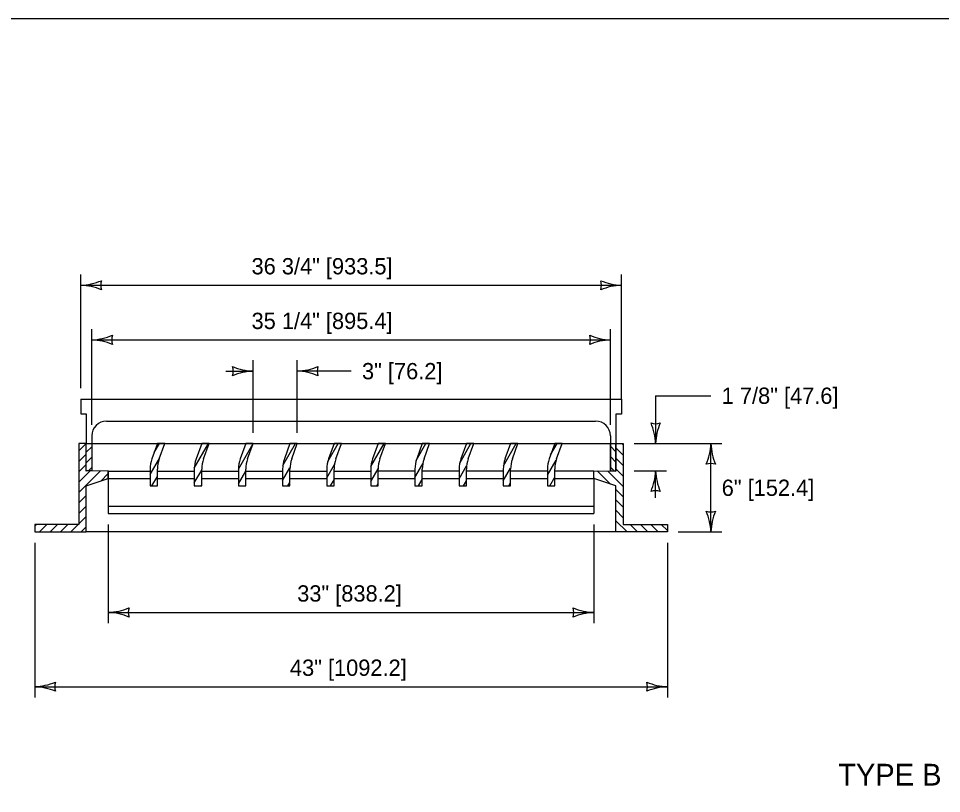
# Model space of a CAD drawing. Extents: x 49991.4 to 50057, y 49987.6 to 50011.4.
# Drawn here: x 50008.526 to 50011.925, y 49996.146 to 49998.999 of the extents above; entities that cross this region are included whole.
import ezdxf

# ---------------------------------------------------------------- set-up
doc = ezdxf.new("R2010")
doc.units = 0
for name, color, linetype in [('Level 1', 7, 'Continuous'), ('Level 2', 7, 'Continuous'), ('Level 3', 7, 'Continuous')]:
    doc.layers.add(name, color=color, linetype=linetype)

msp = doc.modelspace()

# ---------------------------------------------------------------- linework, layer by layer
at = {"layer": 'Level 1'}
for p, q in [((50008.7559, 49997.598), (50008.7559, 49997.5439)), ((50008.7559, 49997.598), (50010.7465, 49997.598)), ((50010.7465, 49997.598), (50010.7465, 49997.5421)), ((50008.7559, 49997.5439), (50008.7762, 49997.5438)), ((50008.7762, 49997.5438), (50008.7762, 49997.4338)), ((50010.7262, 49997.5421), (50010.7262, 49997.4338)), ((50010.7465, 49997.5421), (50010.7262, 49997.5421)), ((50008.8507, 49997.5167), (50010.6518, 49997.5167)), ((50008.7965, 49997.4625), (50008.7965, 49997.4338)), ((50010.7059, 49997.4625), (50010.7059, 49997.3337)), ((50008.7491, 49997.4068), (50008.7761, 49997.4338)), ((50008.7762, 49997.4018), (50008.7965, 49997.4221)), ((50008.7965, 49997.4338), (50010.7059, 49997.4338)), ((50008.7965, 49997.4338), (50008.7965, 49997.3337)), ((50009.0266, 49997.4008), (50009.0456, 49997.4338)), ((50009.174, 49997.3439), (50009.226, 49997.4338)), ((50009.3365, 49997.34), (50009.3906, 49997.4338)), ((50009.4998, 49997.3534), (50009.5462, 49997.4338)), ((50009.6651, 49997.3679), (50009.7031, 49997.4338)), ((50009.8243, 49997.3491), (50009.8732, 49997.4338)), ((50009.9911, 49997.3715), (50010.027, 49997.4338)), ((50010.1513, 49997.3625), (50010.1924, 49997.4338)), ((50010.3121, 49997.3518), (50010.3594, 49997.4338)), ((50010.4858, 49997.392), (50010.51, 49997.4338)), ((50010.7059, 49997.4243), (50010.7262, 49997.404)), ((50010.7262, 49997.4181), (50010.7533, 49997.3911)), ((50010.7488, 49997.4338), (50010.7533, 49997.4294)), ((50008.7491, 49997.3685), (50008.7762, 49997.3956)), ((50008.7762, 49997.3635), (50008.7965, 49997.3838)), ((50009.0115, 49997.3205), (50009.0465, 49997.3812)), ((50010.474, 49997.3173), (50010.5061, 49997.3729)), ((50010.7059, 49997.386), (50010.7262, 49997.3657)), ((50010.7262, 49997.3798), (50010.7533, 49997.3528)), ((50008.7491, 49997.3302), (50008.7762, 49997.3573)), ((50008.7848, 49997.3337), (50008.7965, 49997.3455)), ((50009.174, 49997.2896), (50009.2011, 49997.3365)), ((50009.499, 49997.2978), (50009.5262, 49997.3449)), ((50009.6615, 49997.3075), (50009.6898, 49997.3566)), ((50009.824, 49997.2943), (50009.8511, 49997.3413)), ((50009.9865, 49997.3094), (50010.0152, 49997.3592)), ((50010.149, 49997.3044), (50010.1767, 49997.3525)), ((50010.3115, 49997.2966), (50010.3386, 49997.3436)), ((50010.7059, 49997.3477), (50010.7213, 49997.3323)), ((50010.7262, 49997.3415), (50010.7533, 49997.3144)), ((50008.7491, 49997.2536), (50008.8288, 49997.3333)), ((50008.7491, 49997.2919), (50008.7897, 49997.3325)), ((50008.8298, 49997.296), (50008.8574, 49997.3236)), ((50008.8524, 49997.3035), (50008.8524, 49997.3052)), ((50008.8574, 49997.3323), (50009.0118, 49997.3324)), ((50008.8574, 49997.3323), (50008.8574, 49997.1765)), ((50008.8574, 49997.3052), (50009.0115, 49997.3052)), ((50009.0182, 49997.2781), (50009.0386, 49997.3133)), ((50009.0386, 49997.3052), (50009.174, 49997.3052)), ((50009.0388, 49997.3324), (50009.174, 49997.3325)), ((50009.2011, 49997.3325), (50009.3365, 49997.3326)), ((50009.2011, 49997.3052), (50009.3365, 49997.3052)), ((50009.3365, 49997.2858), (50009.3636, 49997.3328)), ((50009.3636, 49997.3327), (50009.4992, 49997.3328)), ((50009.3636, 49997.3052), (50009.499, 49997.3052)), ((50009.5261, 49997.3328), (50009.6615, 49997.3329)), ((50009.5261, 49997.3052), (50009.6615, 49997.3052)), ((50009.6886, 49997.3329), (50009.824, 49997.333)), ((50009.6886, 49997.3052), (50009.824, 49997.3052)), ((50009.8511, 49997.3331), (50009.9867, 49997.3332)), ((50009.8511, 49997.3052), (50009.9865, 49997.3052)), ((50009.9997, 49997.2781), (50010.0136, 49997.3021)), ((50010.0136, 49997.3332), (50010.1492, 49997.3333)), ((50010.0136, 49997.3052), (50010.149, 49997.3052)), ((50010.1761, 49997.3052), (50010.3115, 49997.3052)), ((50010.1763, 49997.3333), (50010.3117, 49997.3334)), ((50010.3386, 49997.3052), (50010.474, 49997.3052)), ((50010.3388, 49997.3335), (50010.4742, 49997.3336)), ((50010.4826, 49997.2781), (50010.5011, 49997.31)), ((50010.5011, 49997.3052), (50010.6449, 49997.3052)), ((50010.5013, 49997.3336), (50010.6449, 49997.3337)), ((50010.6449, 49997.3079), (50010.649, 49997.3038)), ((50010.6449, 49997.3052), (50010.6449, 49997.1765)), ((50010.65, 49997.3035), (50010.65, 49997.3052)), ((50010.6575, 49997.3336), (50010.7064, 49997.2847)), ((50010.6966, 49997.3328), (50010.7533, 49997.2761)), ((50009.1986, 49997.2781), (50009.2011, 49997.2824)), ((50009.3633, 49997.2781), (50009.3636, 49997.2786)), ((50009.5188, 49997.2781), (50009.5261, 49997.2906)), ((50009.6758, 49997.2781), (50009.6886, 49997.3003)), ((50009.8459, 49997.2781), (50009.8511, 49997.2871)), ((50010.1651, 49997.2781), (50010.1761, 49997.2971)), ((50010.3321, 49997.2781), (50010.3386, 49997.2893)), ((50008.7491, 49997.2153), (50008.7762, 49997.2424)), ((50010.7262, 49997.2649), (50010.7533, 49997.2378)), ((50008.7491, 49997.177), (50008.7762, 49997.2041)), ((50008.8574, 49997.2036), (50010.6449, 49997.2036)), ((50010.7262, 49997.2266), (50010.7533, 49997.1995)), ((50008.7491, 49997.1387), (50008.7762, 49997.1658)), ((50008.8574, 49997.1765), (50010.6449, 49997.1765)), ((50010.7262, 49997.1883), (50010.7533, 49997.1612)), ((50008.5866, 49997.1294), (50008.5931, 49997.1359)), ((50008.6044, 49997.1088), (50008.6314, 49997.1359)), ((50008.6427, 49997.1088), (50008.6697, 49997.1359)), ((50008.681, 49997.1088), (50008.708, 49997.1359)), ((50008.7193, 49997.1088), (50008.7463, 49997.1359)), ((50010.7262, 49997.15), (50010.7674, 49997.1088)), ((50010.7786, 49997.1359), (50010.8057, 49997.1088)), ((50010.8169, 49997.1359), (50010.844, 49997.1088)), ((50010.8552, 49997.1359), (50010.8823, 49997.1088)), ((50010.8935, 49997.1359), (50010.9158, 49997.1136)), ((50008.7576, 49997.1088), (50008.7762, 49997.1275)), ((50010.7262, 49997.1088), (50008.7762, 49997.1088)), ((50010.7262, 49997.1117), (50010.7291, 49997.1088))]:
    msp.add_line(p, q, dxfattribs=at)
for points in [[(49999.3835, 49998.9992), (50016.7501, 49998.9992), (50016.7501, 49987.7988), (49999.3835, 49987.7988)], [(50008.7762, 49997.1088), (50008.7762, 49997.2781), (50008.8574, 49997.3052), (50008.8574, 49997.3338), (50008.7762, 49997.3323), (50008.7762, 49997.4338), (50008.7491, 49997.4338), (50008.7491, 49997.1359), (50008.5866, 49997.1359), (50008.5866, 49997.1088)], [(50008.7762, 49997.4338), (50008.7965, 49997.4338), (50008.7965, 49997.3337), (50008.7762, 49997.3337)], [(50010.7262, 49997.1088), (50010.7262, 49997.2781), (50010.6449, 49997.3052), (50010.6449, 49997.3338), (50010.7262, 49997.3323), (50010.7262, 49997.4338), (50010.7533, 49997.4338), (50010.7533, 49997.1359), (50010.9158, 49997.1359), (50010.9158, 49997.1088)], [(50010.7059, 49997.4338), (50010.7262, 49997.4338), (50010.7262, 49997.3323), (50010.7059, 49997.3323)]]:
    msp.add_lwpolyline(points, close=True, dxfattribs=at)
for points in [[(50009.0451, 49997.3773), (50009.0656, 49997.4338), (50009.0386, 49997.4338), (50009.0386, 49997.4338), (50009.018, 49997.3773)], [(50009.2076, 49997.3773), (50009.2281, 49997.4338), (50009.2011, 49997.4338), (50009.2011, 49997.4338), (50009.1805, 49997.3773)], [(50009.3701, 49997.3773), (50009.3906, 49997.4338), (50009.3636, 49997.4338), (50009.3636, 49997.4338), (50009.343, 49997.3773)], [(50009.5326, 49997.3773), (50009.5531, 49997.4338), (50009.5261, 49997.4338), (50009.5261, 49997.4338), (50009.5055, 49997.3773)], [(50009.6951, 49997.3773), (50009.7156, 49997.4338), (50009.6886, 49997.4338), (50009.6886, 49997.4338), (50009.668, 49997.3773)], [(50009.8576, 49997.3773), (50009.8781, 49997.4338), (50009.8511, 49997.4338), (50009.8511, 49997.4338), (50009.8305, 49997.3773)], [(50010.0201, 49997.3773), (50010.0406, 49997.4338), (50010.0136, 49997.4338), (50010.0136, 49997.4338), (50009.993, 49997.3773)], [(50010.1826, 49997.3773), (50010.2031, 49997.4338), (50010.1761, 49997.4338), (50010.1761, 49997.4338), (50010.1555, 49997.3773)], [(50010.3451, 49997.3773), (50010.3656, 49997.4338), (50010.3386, 49997.4338), (50010.3386, 49997.4338), (50010.318, 49997.3773)], [(50010.5076, 49997.3773), (50010.5281, 49997.4338), (50010.5011, 49997.4338), (50010.5011, 49997.4338), (50010.4805, 49997.3773)], [(50009.0115, 49997.3403), (50009.0115, 49997.2781), (50009.0386, 49997.2781), (50009.0386, 49997.3403)], [(50009.174, 49997.3403), (50009.174, 49997.2781), (50009.2011, 49997.2781), (50009.2011, 49997.3403)], [(50009.3365, 49997.3403), (50009.3365, 49997.2781), (50009.3636, 49997.2781), (50009.3636, 49997.3403)], [(50009.499, 49997.3403), (50009.499, 49997.2781), (50009.5261, 49997.2781), (50009.5261, 49997.3403)], [(50009.6615, 49997.3403), (50009.6615, 49997.2781), (50009.6886, 49997.2781), (50009.6886, 49997.3403)], [(50009.824, 49997.3403), (50009.824, 49997.2781), (50009.8511, 49997.2781), (50009.8511, 49997.3403)], [(50009.9865, 49997.3403), (50009.9865, 49997.2781), (50010.0136, 49997.2781), (50010.0136, 49997.3403)], [(50010.149, 49997.3403), (50010.149, 49997.2781), (50010.1761, 49997.2781), (50010.1761, 49997.3403)], [(50010.3115, 49997.3403), (50010.3115, 49997.2781), (50010.3386, 49997.2781), (50010.3386, 49997.3403)], [(50010.474, 49997.3403), (50010.474, 49997.2781), (50010.5011, 49997.2781), (50010.5011, 49997.3403)]]:
    msp.add_lwpolyline(points, dxfattribs=at)
for centre, radius, start, end in [((50008.8507, 49997.4625), 0.0542, 89.9504, 180), ((50010.6517, 49997.4625), 0.0542, 0, 89.9504), ((50009.1198, 49997.3403), 0.1083, 160.0169, 180), ((50009.1469, 49997.3403), 0.1083, 160.0169, 180), ((50009.2823, 49997.3403), 0.1083, 160.0169, 180), ((50009.3094, 49997.3403), 0.1083, 160.0169, 180), ((50009.4448, 49997.3403), 0.1083, 160.0169, 180), ((50009.4719, 49997.3403), 0.1083, 160.0169, 180), ((50009.6073, 49997.3403), 0.1083, 160.0169, 180), ((50009.6344, 49997.3403), 0.1083, 160.0169, 180), ((50009.7698, 49997.3403), 0.1083, 160.0169, 180), ((50009.7969, 49997.3403), 0.1083, 160.0169, 180), ((50009.9323, 49997.3403), 0.1083, 160.0169, 180), ((50009.9594, 49997.3403), 0.1083, 160.0169, 180), ((50010.0948, 49997.3403), 0.1083, 160.0169, 180), ((50010.1219, 49997.3403), 0.1083, 160.0169, 180), ((50010.2573, 49997.3403), 0.1083, 160.0169, 180), ((50010.2844, 49997.3403), 0.1083, 160.0169, 180), ((50010.4198, 49997.3403), 0.1083, 160.0169, 180), ((50010.4469, 49997.3403), 0.1083, 160.0169, 180), ((50010.5823, 49997.3403), 0.1083, 160.0169, 180), ((50010.6094, 49997.3403), 0.1083, 160.0169, 180)]:
    msp.add_arc(centre, radius, start, end, dxfattribs=at)
at = {"layer": 'Level 3'}
for p, q in [((50008.7559, 49997.638), (50008.7559, 49998.057)), ((50010.7465, 49997.598), (50010.7465, 49998.057)), ((50008.7559, 49998.017), (50010.7465, 49998.017)), ((50008.7965, 49997.5025), (50008.7965, 49997.8558)), ((50010.7059, 49997.5025), (50010.7059, 49997.8558)), ((50008.7965, 49997.8158), (50010.7059, 49997.8158)), ((50009.3906, 49997.4738), (50009.3906, 49997.7407)), ((50009.5531, 49997.4738), (50009.5531, 49997.7407)), ((50009.2906, 49997.7007), (50009.3906, 49997.7007)), ((50009.7515, 49997.7007), (50009.5531, 49997.7007)), ((50010.8726, 49997.6102), (50010.8726, 49997.4338)), ((50010.8726, 49997.6102), (50011.076, 49997.6102)), ((50010.7933, 49997.4338), (50011.116, 49997.4338)), ((50011.076, 49997.1088), (50011.076, 49997.4338)), ((50010.7933, 49997.3337), (50010.9126, 49997.3337)), ((50010.8726, 49997.2337), (50010.8726, 49997.3337)), ((50008.8574, 49997.1365), (50008.8574, 49996.7722)), ((50010.6449, 49997.1365), (50010.6449, 49996.7722)), ((50010.9558, 49997.1088), (50011.116, 49997.1088)), ((50008.5866, 49997.0688), (50008.5866, 49996.4988)), ((50010.9158, 49997.0688), (50010.9158, 49996.4988)), ((50008.8574, 49996.8122), (50010.6449, 49996.8122)), ((50008.5866, 49996.5388), (50010.9158, 49996.5388))]:
    msp.add_line(p, q, dxfattribs=at)
for centre, radius, start, end in [((50008.7444, 49998.2497), 0.233, 272.8273, 292.0772), ((50008.7468, 49997.7948), 0.2223, 67.456, 87.6395), ((50008.8841, 49998.017), 0.0548, 162.1388, 197.8612), ((50010.7557, 49998.2391), 0.2223, 247.456, 267.6395), ((50010.6183, 49998.017), 0.0548, 342.1388, 17.8612), ((50010.7557, 49998.2391), 0.2223, 247.456, 267.6395), ((50010.6183, 49998.017), 0.0548, 342.1388, 17.8612), ((50010.758, 49997.7843), 0.233, 92.8273, 112.0772), ((50010.758, 49997.7843), 0.233, 92.8273, 112.0772), ((50008.785, 49998.0485), 0.233, 272.8273, 292.0772), ((50008.7873, 49997.5936), 0.2223, 67.456, 87.6395), ((50008.9247, 49997.8158), 0.0548, 162.1388, 197.8612), ((50010.715, 49998.0379), 0.2223, 247.456, 267.6395), ((50010.5777, 49997.8158), 0.0548, 342.1388, 17.8612), ((50010.7174, 49997.5831), 0.233, 92.8273, 112.0772), ((50009.3998, 49997.9228), 0.2223, 247.456, 267.6395), ((50009.2624, 49997.7007), 0.0548, 342.1388, 17.8612), ((50009.5416, 49997.9334), 0.233, 272.8273, 292.0772), ((50009.6814, 49997.7007), 0.0548, 162.1388, 197.8612), ((50009.4021, 49997.468), 0.233, 92.8273, 112.0772), ((50009.544, 49997.4786), 0.2223, 67.456, 87.6395), ((50010.8726, 49997.562), 0.0548, 252.1388, 287.8612), ((50010.6398, 49997.4223), 0.233, 2.8273, 22.0772), ((50011.0947, 49997.4247), 0.2223, 157.456, 177.6395), ((50010.8539, 49997.443), 0.2223, 337.456, 357.6395), ((50011.3088, 49997.4453), 0.233, 182.8273, 202.0772), ((50011.076, 49997.3056), 0.0548, 72.1388, 107.8612), ((50010.6504, 49997.3429), 0.2223, 337.456, 357.6395), ((50011.1053, 49997.3452), 0.233, 182.8273, 202.0772), ((50010.8726, 49997.2055), 0.0548, 72.1388, 107.8612), ((50011.076, 49997.237), 0.0548, 252.1388, 287.8612), ((50010.8433, 49997.0973), 0.233, 2.8273, 22.0772), ((50011.2982, 49997.0997), 0.2223, 157.456, 177.6395), ((50008.8459, 49997.0449), 0.233, 272.8273, 292.0772), ((50008.9857, 49996.8122), 0.0548, 162.1388, 197.8612), ((50010.6541, 49997.0343), 0.2223, 247.456, 267.6395), ((50010.5167, 49996.8122), 0.0548, 342.1388, 17.8612), ((50008.8483, 49996.5901), 0.2223, 67.456, 87.6395), ((50010.6564, 49996.5795), 0.233, 92.8273, 112.0772), ((50008.5751, 49996.7715), 0.233, 272.8273, 292.0772), ((50008.7148, 49996.5388), 0.0548, 162.1388, 197.8612), ((50010.9249, 49996.7609), 0.2223, 247.456, 267.6395), ((50010.7876, 49996.5388), 0.0548, 342.1388, 17.8612), ((50008.5774, 49996.3167), 0.2223, 67.456, 87.6395), ((50010.9273, 49996.3061), 0.233, 92.8273, 112.0772)]:
    msp.add_arc(centre, radius, start, end, dxfattribs=at)

# ---------------------------------------------------------------- texts
at = {"layer": 'Level 2'}
for s, height, p in [('36 3/4" [933.5]', 0.06, (50009.3848, 49998.057)), ('35 1/4" [895.4]', 0.06, (50009.3848, 49997.8558)), ('3" [76.2]', 0.06, (50009.7915, 49997.6707)), ('1 7/8" [47.6]', 0.06, (50011.116, 49997.5802)), ('6" [152.4]', 0.06, (50011.116, 49997.2413)), ('33" [838.2]', 0.06, (50009.5529, 49996.8522)), ('43" [1092.2]', 0.06, (50009.5262, 49996.5788)), ('TYPE B', 0.08, (50011.5449, 49996.1749))]:
    msp.add_text(s, height=height, dxfattribs=at).set_placement(p)

doc.saveas('drawing.dxf')
